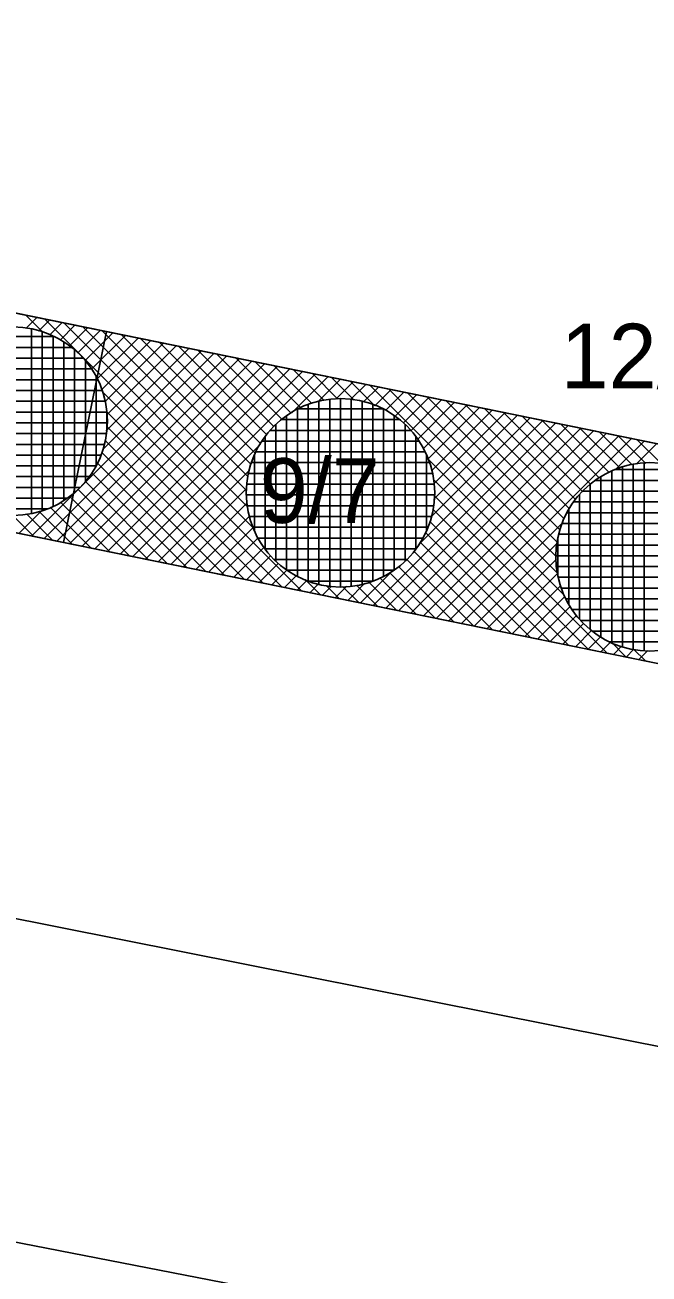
# Model space of a CAD drawing. Extents: x -566461 to -565198, y -1096301 to -1095707.
# Drawn here: x -565834.75 to -565823.16, y -1096125.98 to -1096102.78 of the extents above; entities that cross this region are included whole.
import ezdxf

# ---------------------------------------------------------------- set-up
doc = ezdxf.new("R2010")
doc.units = 0
for name, color, linetype in [('Vrstva 1', 7, 'Continuous'), ('Vrstva 40', 7, 'Continuous'), ('Vrstva 41', 7, 'Continuous'), ('Vrstva 42', 7, 'Continuous'), ('Vrstva 44', 7, 'Continuous')]:
    doc.layers.add(name, color=color, linetype=linetype)

msp = doc.modelspace()

# ---------------------------------------------------------------- linework, layer by layer
at = {"layer": 'Vrstva 1'}
for p, q in [((-565849.04, -1096105.26), (-565748.22, -1096125.78)), ((-565697.28, -1096140.23), (-565854, -1096108.33)), ((-565855.22, -1096115.35), (-565699.29, -1096146.31)), ((-565830.85, -1096126.18), (-565853.27, -1096121.84))]:
    msp.add_line(p, q, dxfattribs=at)
at = {"layer": 'Vrstva 41'}
for p, q in [((-565834.739, -1096108.171), (-565834.42, -1096108.489)), ((-565834.735, -1096108.418), (-565834.53, -1096108.213)), ((-565834.501, -1096108.467), (-565834.295, -1096108.261)), ((-565834.384, -1096108.243), (-565830.503, -1096112.124)), ((-565834.29, -1096108.539), (-565834.06, -1096108.309)), ((-565834.101, -1096108.633), (-565833.825, -1096108.357)), ((-565834.029, -1096108.315), (-565830.61, -1096111.734)), ((-565833.931, -1096108.745), (-565833.59, -1096108.405)), ((-565833.674, -1096108.388), (-565830.63, -1096111.431)), ((-565833.778, -1096108.875), (-565833.355, -1096108.453)), ((-565833.641, -1096109.021), (-565833.12, -1096108.5)), ((-565833.52, -1096109.183), (-565832.885, -1096108.548)), ((-565833.416, -1096109.362), (-565832.65, -1096108.596)), ((-565833.331, -1096109.56), (-565832.415, -1096108.644)), ((-565833.318, -1096108.46), (-565830.605, -1096111.174)), ((-565832.963, -1096108.532), (-565830.55, -1096110.945)), ((-565832.608, -1096108.605), (-565830.472, -1096110.741)), ((-565834.63, -1096112.273), (-565831.24, -1096108.883)), ((-565833.314, -1096110.674), (-565831.475, -1096108.835)), ((-565833.268, -1096109.779), (-565832.18, -1096108.692)), ((-565833.25, -1096110.327), (-565831.71, -1096108.787)), ((-565833.236, -1096110.03), (-565831.945, -1096108.74)), ((-565832.253, -1096108.677), (-565830.372, -1096110.558)), ((-565831.898, -1096108.749), (-565830.256, -1096110.391)), ((-565831.543, -1096108.821), (-565830.123, -1096110.242)), ((-565834.395, -1096112.321), (-565831.005, -1096108.931)), ((-565834.16, -1096112.368), (-565830.77, -1096108.979)), ((-565833.925, -1096112.416), (-565830.535, -1096109.027)), ((-565833.69, -1096112.464), (-565830.3, -1096109.074)), ((-565833.455, -1096112.512), (-565830.065, -1096109.122)), ((-565831.188, -1096108.894), (-565829.973, -1096110.108)), ((-565830.833, -1096108.966), (-565829.807, -1096109.991)), ((-565830.477, -1096109.038), (-565829.625, -1096109.891)), ((-565830.122, -1096109.111), (-565829.422, -1096109.811)), ((-565833.22, -1096112.56), (-565829.83, -1096109.17)), ((-565832.985, -1096112.608), (-565829.595, -1096109.218)), ((-565832.75, -1096112.655), (-565829.36, -1096109.266)), ((-565829.794, -1096109.982), (-565829.125, -1096109.314)), ((-565829.767, -1096109.183), (-565829.193, -1096109.757)), ((-565829.412, -1096109.255), (-565828.937, -1096109.73)), ((-565829.057, -1096109.327), (-565828.636, -1096109.749)), ((-565829.31, -1096109.782), (-565828.89, -1096109.361)), ((-565828.978, -1096109.732), (-565828.655, -1096109.409)), ((-565828.702, -1096109.4), (-565828.25, -1096109.852)), ((-565828.701, -1096109.738), (-565828.42, -1096109.457)), ((-565828.463, -1096109.783), (-565828.185, -1096109.505)), ((-565828.347, -1096109.472), (-565824.852, -1096112.967)), ((-565828.249, -1096109.852), (-565827.95, -1096109.553)), ((-565827.992, -1096109.544), (-565824.881, -1096112.655)), ((-565833.319, -1096109.59), (-565829.617, -1096113.293)), ((-565828.056, -1096109.942), (-565827.715, -1096109.601)), ((-565827.882, -1096110.05), (-565827.48, -1096109.648)), ((-565827.724, -1096110.175), (-565827.245, -1096109.696)), ((-565827.636, -1096109.617), (-565824.858, -1096112.395)), ((-565827.584, -1096110.318), (-565827.01, -1096109.744)), ((-565827.46, -1096110.477), (-565826.775, -1096109.792)), ((-565827.281, -1096109.689), (-565824.807, -1096112.163)), ((-565826.926, -1096109.761), (-565824.731, -1096111.956)), ((-565833.241, -1096109.952), (-565829.972, -1096113.221)), ((-565827.353, -1096110.653), (-565826.54, -1096109.84)), ((-565827.265, -1096110.848), (-565826.305, -1096109.888)), ((-565827.198, -1096111.063), (-565826.07, -1096109.935)), ((-565827.161, -1096111.592), (-565825.6, -1096110.031)), ((-565827.156, -1096111.304), (-565825.835, -1096109.983)), ((-565826.571, -1096109.833), (-565824.635, -1096111.77)), ((-565826.216, -1096109.906), (-565824.52, -1096111.602)), ((-565825.861, -1096109.978), (-565824.389, -1096111.45)), ((-565825.506, -1096110.05), (-565824.241, -1096111.315)), ((-565833.24, -1096110.235), (-565830.327, -1096113.149)), ((-565828.285, -1096113.564), (-565824.895, -1096110.175)), ((-565828.05, -1096113.612), (-565824.66, -1096110.222)), ((-565827.815, -1096113.66), (-565824.425, -1096110.27)), ((-565827.448, -1096112.445), (-565825.13, -1096110.127)), ((-565827.211, -1096111.925), (-565825.365, -1096110.079)), ((-565825.151, -1096110.123), (-565824.077, -1096111.196)), ((-565824.795, -1096110.195), (-565823.896, -1096111.094)), ((-565824.44, -1096110.267), (-565823.696, -1096111.011)), ((-565833.267, -1096110.491), (-565830.682, -1096113.076)), ((-565827.58, -1096113.708), (-565824.19, -1096110.318)), ((-565827.345, -1096113.756), (-565823.955, -1096110.366)), ((-565827.11, -1096113.803), (-565823.72, -1096110.414)), ((-565826.875, -1096113.851), (-565823.485, -1096110.462)), ((-565824.085, -1096110.339), (-565823.472, -1096110.952)), ((-565823.787, -1096111.046), (-565823.25, -1096110.509)), ((-565823.73, -1096110.412), (-565823.218, -1096110.923)), ((-565823.375, -1096110.484), (-565822.925, -1096110.934)), ((-565833.328, -1096110.713), (-565831.037, -1096113.004)), ((-565832.515, -1096112.703), (-565830.378, -1096110.566)), ((-565823.399, -1096110.941), (-565823.015, -1096110.557)), ((-565833.413, -1096110.911), (-565831.392, -1096112.932)), ((-565827.272, -1096110.83), (-565824.726, -1096113.375)), ((-565833.516, -1096111.091), (-565831.747, -1096112.859)), ((-565832.28, -1096112.751), (-565830.578, -1096111.05)), ((-565833.773, -1096111.4), (-565832.458, -1096112.715)), ((-565833.636, -1096111.254), (-565832.103, -1096112.787)), ((-565832.045, -1096112.799), (-565830.628, -1096111.382)), ((-565827.169, -1096111.216), (-565823.935, -1096114.45)), ((-565834.095, -1096111.644), (-565833.168, -1096112.57)), ((-565833.925, -1096111.53), (-565832.813, -1096112.643)), ((-565831.81, -1096112.847), (-565830.622, -1096111.659)), ((-565827.153, -1096111.514), (-565824.29, -1096114.377)), ((-565834.991, -1096111.879), (-565834.588, -1096112.281)), ((-565834.865, -1096112.225), (-565834.436, -1096111.796)), ((-565834.726, -1096111.86), (-565834.233, -1096112.353)), ((-565834.493, -1096111.811), (-565833.878, -1096112.426)), ((-565834.283, -1096111.738), (-565833.523, -1096112.498)), ((-565831.575, -1096112.895), (-565830.577, -1096111.897)), ((-565827.18, -1096111.77), (-565824.645, -1096114.305)), ((-565831.34, -1096112.942), (-565830.508, -1096112.111)), ((-565827.231, -1096112.002), (-565825, -1096114.233)), ((-565826.64, -1096113.899), (-565824.754, -1096112.013)), ((-565831.105, -1096112.99), (-565830.418, -1096112.304)), ((-565827.311, -1096112.205), (-565825.355, -1096114.161)), ((-565830.87, -1096113.038), (-565830.31, -1096112.478)), ((-565827.528, -1096112.553), (-565826.065, -1096114.016)), ((-565827.411, -1096112.387), (-565825.71, -1096114.088)), ((-565826.405, -1096113.947), (-565824.859, -1096112.401)), ((-565830.635, -1096113.086), (-565830.185, -1096112.636)), ((-565830.4, -1096113.134), (-565830.042, -1096112.776)), ((-565827.811, -1096112.836), (-565826.776, -1096113.871)), ((-565827.662, -1096112.703), (-565826.42, -1096113.944)), ((-565826.17, -1096113.995), (-565824.879, -1096112.704)), ((-565830.165, -1096113.182), (-565829.883, -1096112.9)), ((-565829.93, -1096113.229), (-565829.707, -1096113.007)), ((-565828.52, -1096113.516), (-565827.915, -1096112.912)), ((-565828.161, -1096113.052), (-565827.486, -1096113.727)), ((-565827.978, -1096112.952), (-565827.131, -1096113.799)), ((-565825.935, -1096114.043), (-565824.853, -1096112.961)), ((-565829.695, -1096113.277), (-565829.512, -1096113.095)), ((-565829.544, -1096113.083), (-565829.261, -1096113.365)), ((-565829.46, -1096113.325), (-565829.297, -1096113.162)), ((-565829.225, -1096113.373), (-565829.056, -1096113.204)), ((-565829.154, -1096113.19), (-565828.906, -1096113.438)), ((-565828.99, -1096113.421), (-565828.775, -1096113.206)), ((-565828.851, -1096113.21), (-565828.551, -1096113.51)), ((-565828.755, -1096113.469), (-565828.435, -1096113.149)), ((-565828.594, -1096113.185), (-565828.196, -1096113.582)), ((-565828.365, -1096113.13), (-565827.841, -1096113.655)), ((-565825.7, -1096114.09), (-565824.798, -1096113.189)), ((-565825.465, -1096114.138), (-565824.718, -1096113.392)), ((-565825.23, -1096114.186), (-565824.619, -1096113.575)), ((-565824.995, -1096114.234), (-565824.501, -1096113.741)), ((-565824.76, -1096114.282), (-565824.368, -1096113.891)), ((-565824.525, -1096114.33), (-565824.218, -1096114.024)), ((-565824.29, -1096114.377), (-565824.052, -1096114.14)), ((-565824.055, -1096114.425), (-565823.869, -1096114.24)), ((-565823.855, -1096114.246), (-565823.579, -1096114.522)), ((-565823.82, -1096114.473), (-565823.666, -1096114.319)), ((-565823.584, -1096114.521), (-565823.437, -1096114.373)), ((-565823.447, -1096114.372), (-565823.224, -1096114.594)), ((-565823.349, -1096114.569), (-565823.179, -1096114.399))]:
    msp.add_line(p, q, dxfattribs=at)
at = {"layer": 'Vrstva 42'}
msp.add_line((-565833.237, -1096108.476), (-565834.034, -1096112.394), dxfattribs=at)
msp.add_lwpolyline([(-565828.2, -1096027.12), (-565826.72, -1096023.51), (-565829.55, -1096025.32), (-565832.07, -1096026.09), (-565854, -1096108.33), (-565697.28, -1096140.23), (-565696.05, -1096136.4), (-565849.04, -1096105.26)], close=True, dxfattribs=at)
at = {"layer": 'Vrstva 44'}
for p, q in [((-565834.63, -1096111.855), (-565834.63, -1096108.424)), ((-565834.201, -1096108.57), (-565835.742, -1096108.57)), ((-565834.43, -1096111.803), (-565834.43, -1096108.476)), ((-565834.23, -1096111.725), (-565834.23, -1096108.556)), ((-565833.883, -1096108.77), (-565836.057, -1096108.77)), ((-565834.03, -1096111.614), (-565834.03, -1096108.665)), ((-565833.83, -1096111.466), (-565833.83, -1096108.814)), ((-565833.671, -1096108.97), (-565836.271, -1096108.97)), ((-565833.63, -1096111.263), (-565833.63, -1096109.015)), ((-565833.515, -1096109.17), (-565836.424, -1096109.17)), ((-565833.43, -1096110.967), (-565833.43, -1096109.31)), ((-565833.317, -1096109.57), (-565836.624, -1096109.57)), ((-565833.401, -1096109.37), (-565836.54, -1096109.37)), ((-565833.26, -1096109.77), (-565836.679, -1096109.77)), ((-565829.29, -1096113.173), (-565829.29, -1096109.768)), ((-565829.09, -1096113.208), (-565829.09, -1096109.733)), ((-565828.89, -1096113.218), (-565828.89, -1096109.721)), ((-565828.69, -1096113.207), (-565828.69, -1096109.732)), ((-565828.49, -1096113.172), (-565828.49, -1096109.768)), ((-565833.23, -1096109.97), (-565836.71, -1096109.97)), ((-565833.23, -1096110.31), (-565833.23, -1096109.968)), ((-565829.89, -1096112.904), (-565829.89, -1096110.036)), ((-565829.69, -1096113.026), (-565829.69, -1096109.914)), ((-565828.1, -1096109.91), (-565829.682, -1096109.91)), ((-565829.49, -1096113.112), (-565829.49, -1096109.827)), ((-565828.29, -1096113.114), (-565828.29, -1096109.828)), ((-565828.09, -1096113.025), (-565828.09, -1096109.915)), ((-565827.89, -1096112.904), (-565827.89, -1096110.036)), ((-565833.222, -1096110.17), (-565836.718, -1096110.17)), ((-565830.09, -1096112.743), (-565830.09, -1096110.197)), ((-565827.789, -1096110.11), (-565829.989, -1096110.11)), ((-565827.69, -1096112.742), (-565827.69, -1096110.198)), ((-565833.237, -1096110.37), (-565836.704, -1096110.37)), ((-565827.428, -1096110.51), (-565830.351, -1096110.51)), ((-565830.29, -1096112.517), (-565830.29, -1096110.422)), ((-565827.582, -1096110.31), (-565830.2, -1096110.31)), ((-565827.49, -1096112.52), (-565827.49, -1096110.423)), ((-565833.275, -1096110.57), (-565836.665, -1096110.57)), ((-565827.316, -1096110.71), (-565830.465, -1096110.71)), ((-565833.338, -1096110.77), (-565836.601, -1096110.77)), ((-565833.432, -1096110.97), (-565836.509, -1096110.97)), ((-565827.233, -1096110.91), (-565830.547, -1096110.91)), ((-565830.49, -1096112.178), (-565830.49, -1096110.765)), ((-565827.29, -1096112.174), (-565827.29, -1096110.762)), ((-565823.45, -1096114.38), (-565823.45, -1096110.938)), ((-565823.25, -1096114.405), (-565823.25, -1096110.915)), ((-565833.556, -1096111.17), (-565836.383, -1096111.17)), ((-565827.178, -1096111.11), (-565830.601, -1096111.11)), ((-565824.05, -1096114.153), (-565824.05, -1096111.166)), ((-565823.85, -1096114.257), (-565823.85, -1096111.063)), ((-565822.48, -1096111.04), (-565823.799, -1096111.04)), ((-565823.65, -1096114.333), (-565823.65, -1096110.987)), ((-565833.728, -1096111.37), (-565836.213, -1096111.37)), ((-565827.149, -1096111.31), (-565830.631, -1096111.31)), ((-565821.887, -1096111.44), (-565824.392, -1096111.44)), ((-565824.25, -1096114.011), (-565824.25, -1096111.309)), ((-565822.12, -1096111.24), (-565824.16, -1096111.24)), ((-565833.964, -1096111.57), (-565835.975, -1096111.57)), ((-565827.142, -1096111.51), (-565830.638, -1096111.51)), ((-565821.72, -1096111.64), (-565824.561, -1096111.64)), ((-565824.45, -1096113.819), (-565824.45, -1096111.5)), ((-565834.336, -1096111.77), (-565835.605, -1096111.77)), ((-565827.158, -1096111.71), (-565830.623, -1096111.71)), ((-565821.595, -1096111.84), (-565824.684, -1096111.84)), ((-565824.65, -1096113.543), (-565824.65, -1096111.776)), ((-565827.197, -1096111.91), (-565830.582, -1096111.91)), ((-565827.263, -1096112.11), (-565830.517, -1096112.11)), ((-565821.506, -1096112.04), (-565824.775, -1096112.04)), ((-565827.357, -1096112.31), (-565830.424, -1096112.31)), ((-565824.85, -1096113.025), (-565824.85, -1096112.297)), ((-565821.443, -1096112.24), (-565824.839, -1096112.24)), ((-565827.483, -1096112.51), (-565830.296, -1096112.51)), ((-565821.404, -1096112.44), (-565824.875, -1096112.44)), ((-565827.658, -1096112.71), (-565830.123, -1096112.71)), ((-565821.391, -1096112.64), (-565824.888, -1096112.64)), ((-565827.899, -1096112.91), (-565829.881, -1096112.91)), ((-565821.401, -1096112.84), (-565824.879, -1096112.84)), ((-565821.434, -1096113.04), (-565824.847, -1096113.04)), ((-565828.28, -1096113.11), (-565829.496, -1096113.11)), ((-565821.49, -1096113.24), (-565824.79, -1096113.24)), ((-565821.574, -1096113.44), (-565824.704, -1096113.44)), ((-565821.693, -1096113.64), (-565824.588, -1096113.64)), ((-565821.848, -1096113.84), (-565824.43, -1096113.84)), ((-565822.066, -1096114.04), (-565824.215, -1096114.04)), ((-565822.389, -1096114.24), (-565823.888, -1096114.24))]:
    msp.add_line(p, q, dxfattribs=at)
for centre in [(-565834.97, -1096110.14), (-565828.89, -1096111.47), (-565823.14, -1096112.66)]:
    msp.add_circle(centre, 1.75, dxfattribs=at)

# ---------------------------------------------------------------- texts
at = {"layer": 'Vrstva 40'}
for s, p in [('12/60', (-565824.8, -1096109.53)), ('9/7', (-565830.39, -1096112.03))]:
    msp.add_text(s, height=1.2, dxfattribs=at).set_placement(p)

doc.saveas('drawing.dxf')
